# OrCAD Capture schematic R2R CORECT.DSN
size A
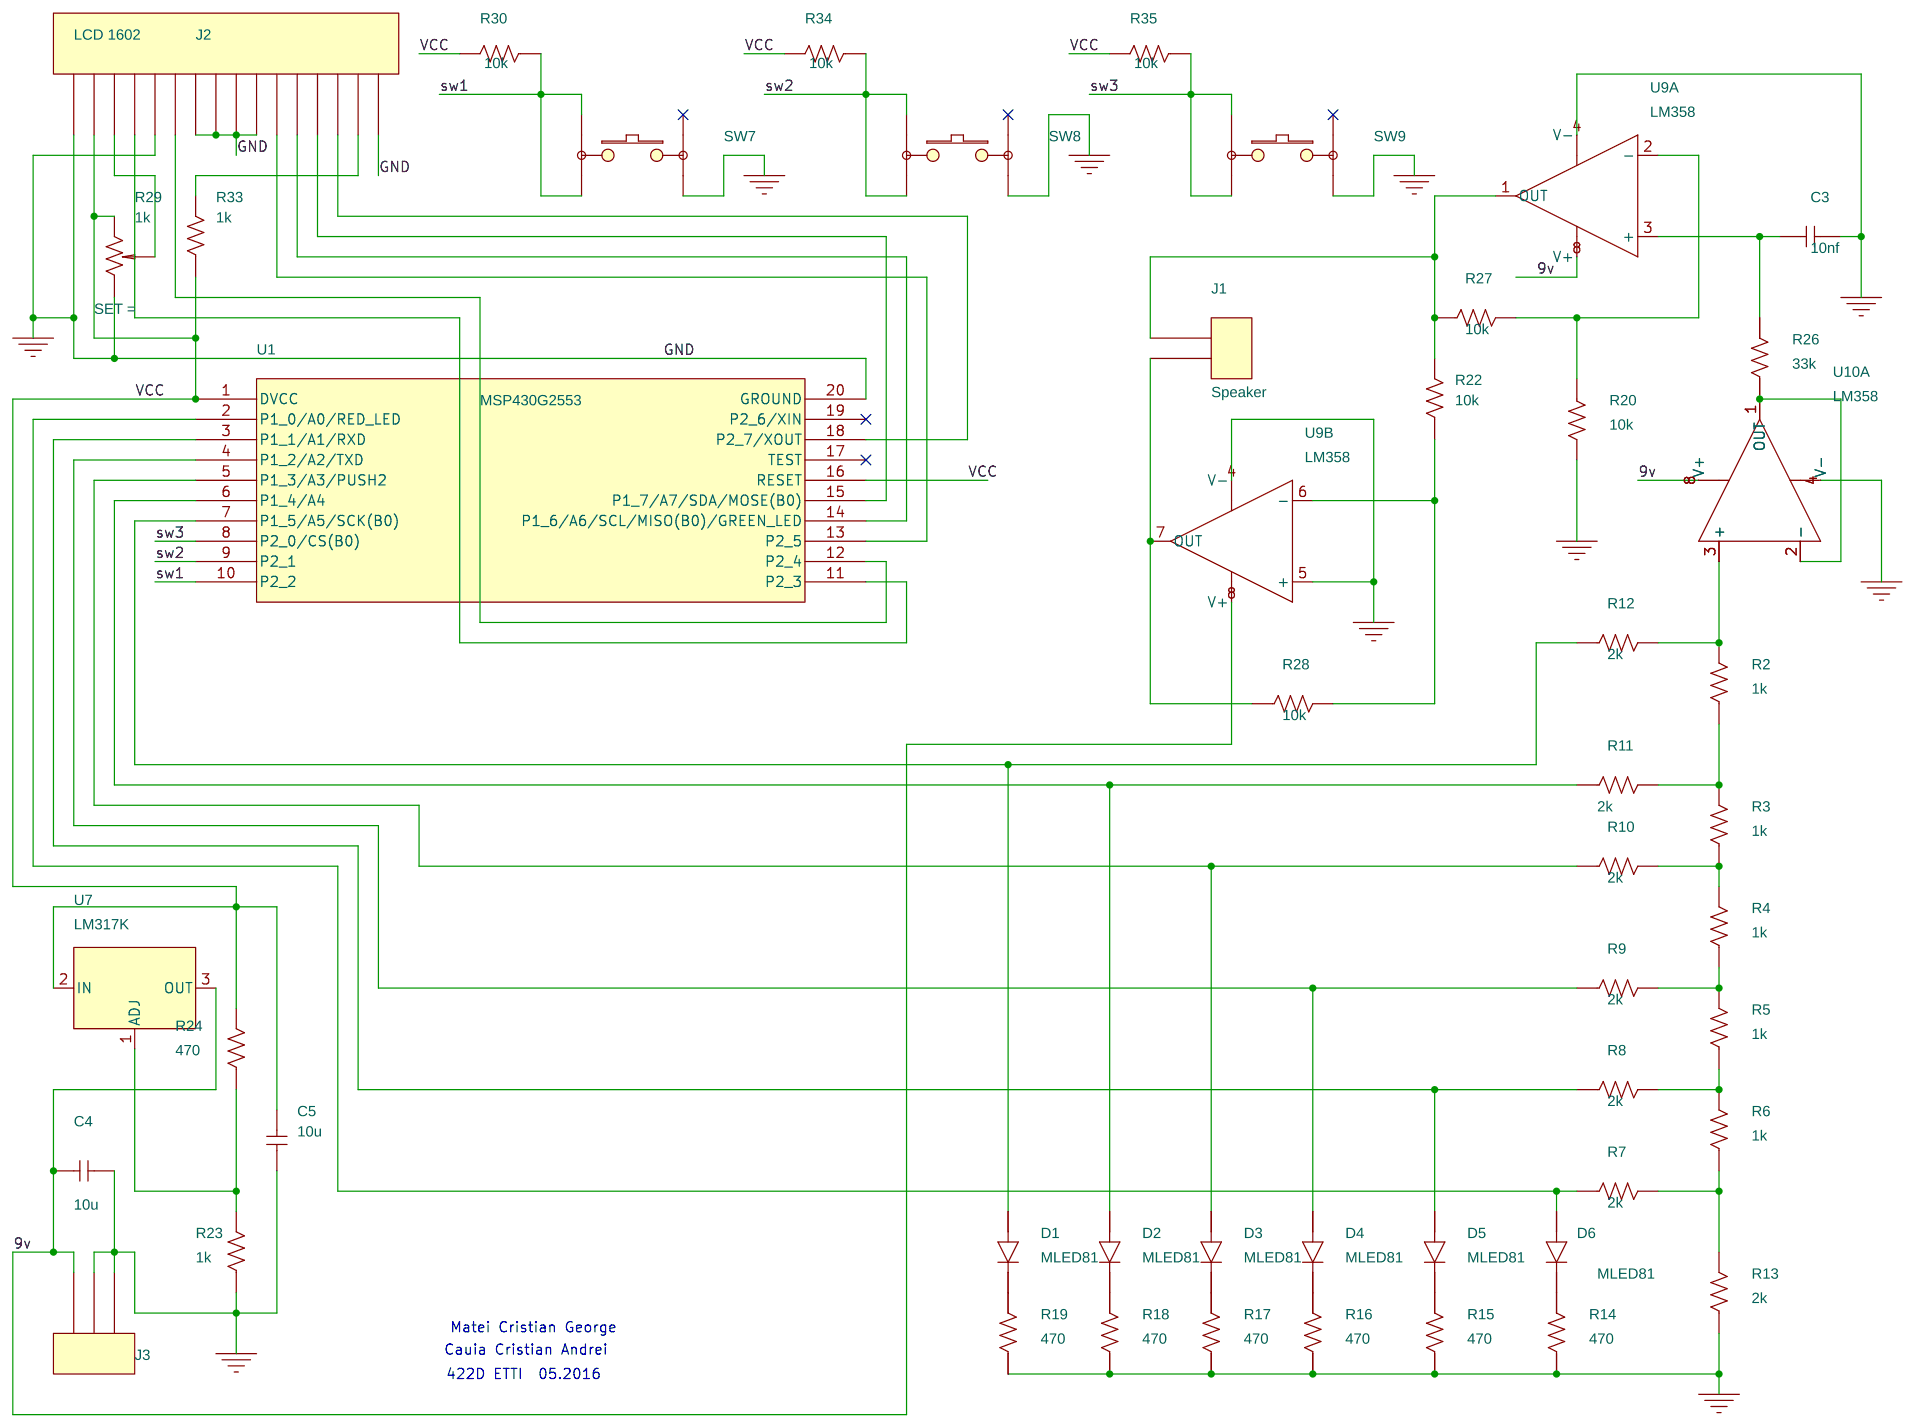
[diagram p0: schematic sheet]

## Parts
C3  10nf  [capck05]
C4  10u  [capck05]
C5  10u  [capck05]
D1  MLED81  [jumper2]
D2  MLED81  [jumper2]
D3  MLED81  [jumper2]
D4  MLED81  [jumper2]
D5  MLED81  [jumper2]
D6  MLED81  [jumper2]
J1  Speaker  [jumper2]
J2  LCD 1602  [sip16]
J3  CON3  [jack_dc2]
R2  1k  [res400]
R3  1k  [res400]
R4  1k  [res400]
R5  1k  [res400]
R6  1k  [res400]
R7  2k  [res400]
R8  2k  [res400]
R9  2k  [res400]
R10  2k  [res400]
R11  2k  [res400]
R12  2k  [res400]
R13  2k  [res400]
R14  470  [res400]
R15  470  [res400]
R16  470  [res400]
R17  470  [res400]
R18  470  [res400]
R19  470  [res400]
R20  10k  [res400]
R22  10k  [res400]
R23  1k  [res400]
R24  470  [res400]
R26  33k  [res400]
R27  10k  [res400]
R28  10k  [res400]
R29  1k  [jumper3]
R30  10k  [res400]
R33  1k  [res400]
R34  10k  [res400]
R35  10k  [res400]
SW7  SW_TC_SPST  [SW_SCHURTER_13019306L]
SW8  SW_TC_SPST  [SW_SCHURTER_13019306L]
SW9  SW_TC_SPST  [SW_SCHURTER_13019306L]
U1  MSP430G2553  [dip20]
U7  LM317K  [to220ab]
U9  LM358  [dip8_3]  (sections A,B)
U10  LM358  [dip8_3]  (section A)

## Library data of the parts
C3 = C: SIGNAL_MODEL: DEFAULT_CAPACITOR_10000pF_1_2
C4 C5 = C: SIGNAL_MODEL: DEFAULT_CAPACITOR_1e+07pF_1_2
D1-D6 = MLED81
J1 = CON2
J2 = CON16
J3 = CON3
R2-R6 R23 R33 = R: SIGNAL_MODEL: DEFAULT_RESISTOR_1000OHM_2_1
R7-R13 = R: SIGNAL_MODEL: DEFAULT_RESISTOR_2000OHM_2_1
R14-R19 R24 = R: SIGNAL_MODEL: DEFAULT_RESISTOR_470OHM_2_1
R20 R22 R27 R28 R30 R34 R35 = R: SIGNAL_MODEL: DEFAULT_RESISTOR_10000OHM_2_1
R26 = R: SIGNAL_MODEL: DEFAULT_RESISTOR_33000OHM_2_1
R29 = POT
SW7-SW9 = SW_TC_SPST
U1 = MSP430G2553_4
U7 = LM317T_0
U9 = LM358
U10 = LM358_0

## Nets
9v: C4.2 J3.1 U7.3(OUT) U9.8(V+) U10.8(V+)
VCC: C5.2 J2.2 R24.2 R29.3(2) R30.2 R33.1 R34.2 R35.2 U1.1(DVCC) U1.16(RESET) U7.2(IN)
0: C3.2 C4.1 C5.1 J2.1 J2.5 J2.7 J2.8 J2.9 J2.10 J2.16 J3.2 J3.3 R13.1 R14.1 R15.1 R16.1 R17.1 R18.1 R19.1 R20.2 R23.1 R29.1 SW7.3 SW8.3 SW9.3 U1.20(GROUND) U9.4(V-) U9.5(+) U10.4(V-)
sw1: R30.1 SW7.1 SW7.2 U1.10(P2_2)
sw2: R34.1 SW8.1 SW8.2 U1.9(P2_1)
sw3: R35.1 SW9.1 SW9.2 U1.8(P2_0/CS(B0))
N00328: R2.1 R3.2 R11.2
N00336: R4.1 R5.2 R9.2
N00340: R5.1 R6.2 R8.2
N00355: R2.2 R12.2 U10.3(+)
N00395: R3.1 R4.2 R10.2
N00470: R6.1 R7.2 R13.2
N01662: D5.1(A) R8.1 U1.3(P1_1/A1/RXD)
N01669: D4.1(A) R9.1 U1.4(P1_2/A2/TXD)
N01683: D2.1(A) R11.1 U1.6(P1_4/A4)
N01690: D1.1(A) R12.1 U1.7(P1_5/A5/SCK(B0))
N01717: D3.1(A) R10.1 U1.5(P1_3/A3/PUSH2)
N20855: R23.2 R24.1 U7.1(ADJ)
N23488: C3.1 R26.2 U9.3(+)
N23661: R26.1 U10.1(OUT) U10.2(-)
N24189: R20.1 R27.2 U9.2(-)
N24193: J1.1 R22.2 R27.1 U9.1(OUT)
N25824: R22.1 R28.2 U9.6(-)
N25853: J1.2 R28.1 U9.7(OUT)
N29134: D6.1(A) R7.1 U1.2(P1_0/A0/RED_LED)
N35057: J2.3 R29.2(t)
N35516: J2.4 U1.11(P2_3)
N35592: J2.6 U1.12(P2_4)
N35638: J2.11 U1.13(P2_5)
N35656: J2.12 U1.14(P1_6/A6/SCL/MISO(B0)/GREEN_LED)
N35674: J2.13 U1.15(P1_7/A7/SDA/MOSE(B0))
N35692: J2.14 U1.18(P2_7/XOUT)
N35721: J2.15 R33.2
N72092: D3.2(C) R17.2
N72093: D2.2(C) R18.2
N72094: D6.2(C) R14.2
N72095: D1.2(C) R19.2
N72096: D4.2(C) R16.2
N72097: D5.2(C) R15.2

Not connected (* = marked no-connect by the designer): SW7 4*; SW8 4*; SW9 4*; U1 17(TEST)* 19(P2_6/XIN)*

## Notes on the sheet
- Cauia Cristian Andrei
- Matei Cristian George
- 422D ETTI  05.2016
